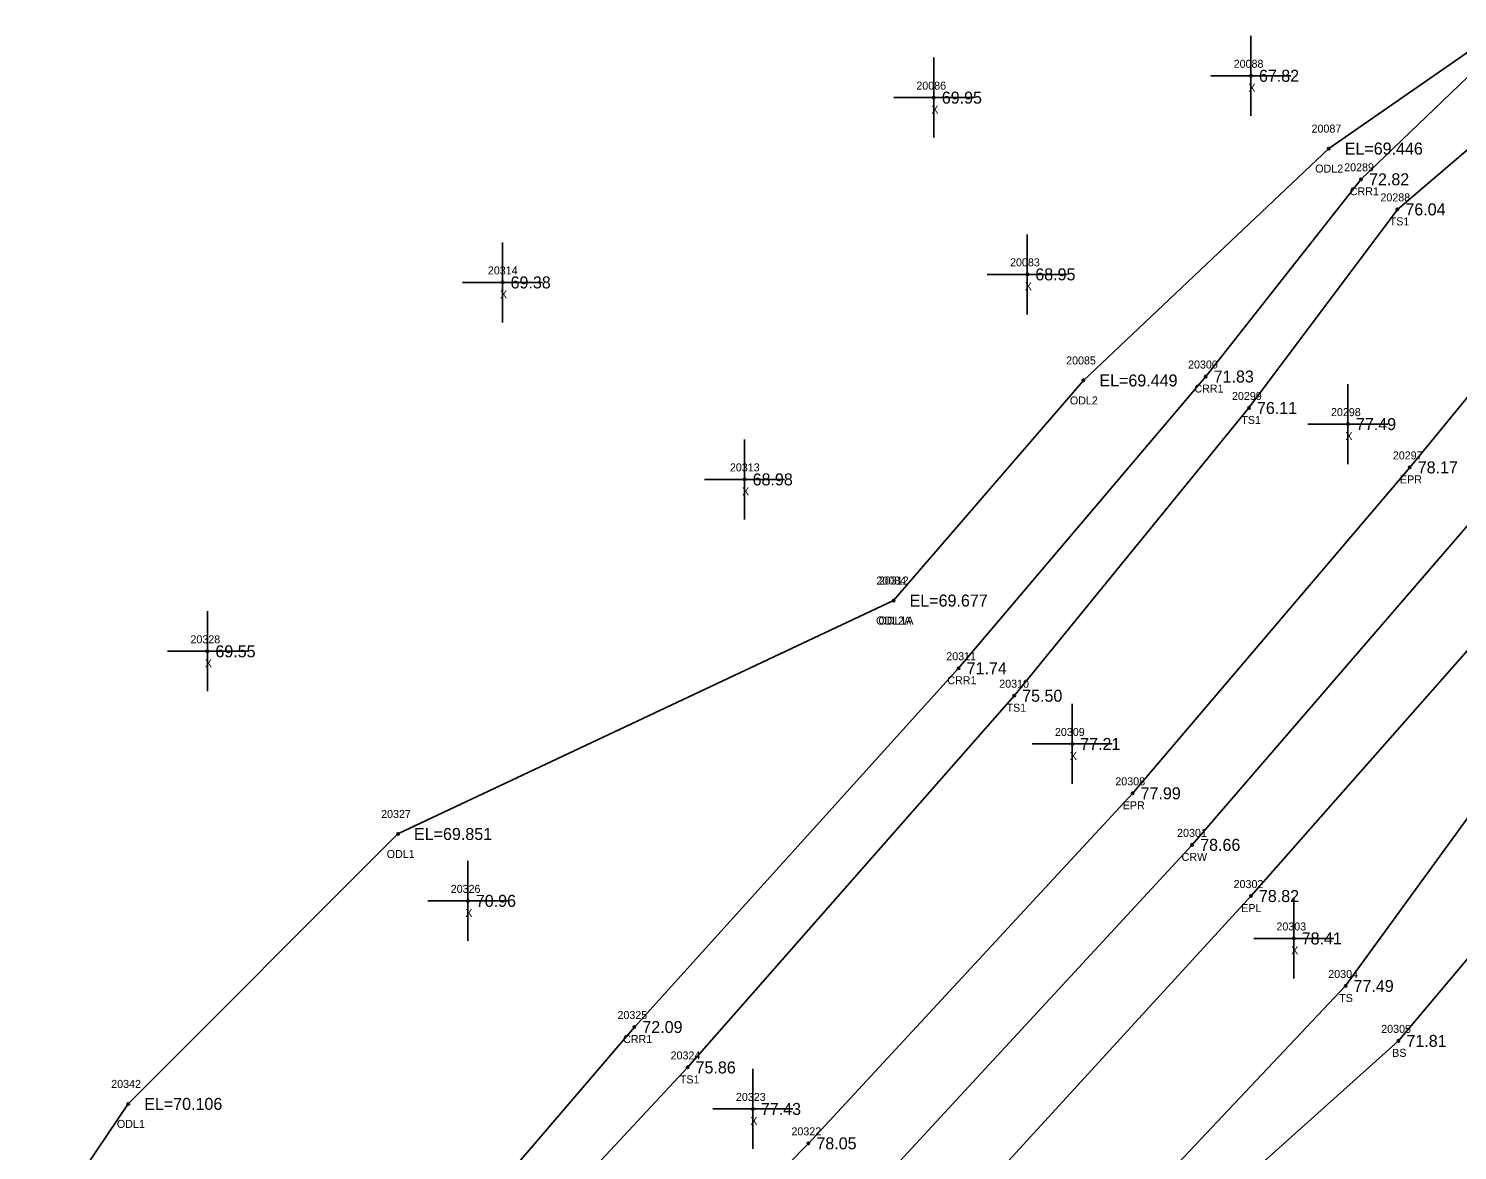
# Model space of a CAD drawing. Extents: x 2505300 to 2506184, y 912965 to 913825.
# Drawn here: x 2505552.8 to 2505731.4, y 913342.5 to 913482.7 of the extents above; entities that cross this region are included whole.
import ezdxf

# ---------------------------------------------------------------- set-up
doc = ezdxf.new("R2010")
doc.units = 0
for name, color, linetype in [('RD_DTM_BkLn1', 7, 'Continuous'), ('RD_DTM_BkLn2', 7, 'Continuous'), ('RD_DTM_BkLn_txCode', 7, 'Continuous'), ('RD_EX_H2O', 7, 'Continuous'), ('RD_EX_H2O_txCode', 7, 'Continuous'), ('RD_EX_Misc', 7, 'Continuous'), ('RD_EX_Misc_txCode', 7, 'Continuous'), ('RD_EX_Road', 7, 'Continuous'), ('RD_EX_Road_txCode', 7, 'Continuous'), ('RD_EX_TX_H2O_ELEV', 7, 'Continuous'), ('RD_EX_TX_Misc_ELEV', 7, 'Continuous'), ('RD_EX_TX_Road_ELEV', 7, 'Continuous'), ('RD_HC_Survey_ELEV', 7, 'Continuous'), ('RD_HC_Survey_txCode', 7, 'Continuous'), ('RD_SMD_Locator', 7, 'Continuous')]:
    doc.layers.add(name, color=color, linetype=linetype)

msp = doc.modelspace()

# ---------------------------------------------------------------- linework, layer by layer
at = {"layer": 'RD_DTM_BkLn1'}
msp.add_lwpolyline([(2505767.92, 913463.52), (2505733.49, 913421.6), (2505698.21, 913380.67), (2505657.08, 913336.16), (2505615.28, 913294.08), (2505578.04, 913257.66), (2505509.81, 913190.87), (2505437.56, 913120.73), (2505363.23, 913048.54)], dxfattribs=at)
at = {"layer": 'RD_DTM_BkLn2'}
for points in [[(2505753.71, 913473.94), (2505744.94, 913478.08), (2505723.86, 913460.1), (2505705.31, 913435.28), (2505675.97, 913399.31), (2505635.15, 913352.85), (2505596.03, 913310.85), (2505561.37, 913275.87), (2505492.57, 913207.56), (2505417.69, 913144.74), (2505344.31, 913068.67)], [(2505795.69, 913463.1), (2505792.51, 913445.22), (2505759.98, 913398.97), (2505723.99, 913356.17), (2505679.61, 913316.33), (2505634.47, 913275.19), (2505602.54, 913232.97), (2505592.24, 913228.82), (2505620.93, 913209.9)], [(2505778.84, 913452.68), (2505749.61, 913407.4), (2505717.38, 913363.03), (2505676.27, 913319.47), (2505630.56, 913278.36), (2505596.33, 913240.71), (2505582.14, 913231.32), (2505618.19, 913208.73)]]:
    msp.add_lwpolyline(points, dxfattribs=at)
at = {"layer": 'RD_EX_H2O'}
for points in [[(2505660.9, 913411.21), (2505684.62, 913438.72), (2505715.28, 913467.7), (2505742.46, 913486.6), (2505763.96, 913488.43), (2505794.61, 913469.83), (2505812.57, 913467.2), (2505833.64, 913450.28), (2505872.88, 913457.34), (2505893.17, 913479.86), (2505942.46, 913480.08), (2505995.98, 913475.04), (2506045.33, 913460.93), (2506077.87, 913439.29), (2506087.99, 913429.78), (2506108.19, 913381.27)], [(2505789.47, 913464.31), (2505758.18, 913486.1), (2505736.66, 913480.49), (2505719.32, 913463.86), (2505699.9, 913439.21), (2505669.03, 913402.75), (2505628.5, 913357.9), (2505593, 913316.39), (2505556.58, 913279.8), (2505487.72, 913211.38), (2505413.81, 913149.81), (2505341.31, 913072.1)], [(2505660.9, 913411.21), (2505598.96, 913382.03), (2505565.24, 913348.29), (2505539.28, 913309.84), (2505469.64, 913225.59)]]:
    msp.add_lwpolyline(points, dxfattribs=at)
at = {"layer": 'RD_EX_Misc'}
for p, q in [((2505705.56, 913471.8), (2505705.56, 913481.8)), ((2505665.92, 913469.07), (2505665.92, 913479.07)), ((2505700.56, 913476.8), (2505710.56, 913476.8)), ((2505660.92, 913474.07), (2505670.92, 913474.07)), ((2505677.61, 913446.98), (2505677.61, 913456.98)), ((2505612.03, 913445.97), (2505612.03, 913455.97)), ((2505607.03, 913450.97), (2505617.03, 913450.97)), ((2505672.61, 913451.98), (2505682.61, 913451.98)), ((2505717.68, 913428.26), (2505717.68, 913438.26)), ((2505712.68, 913433.26), (2505722.68, 913433.26)), ((2505642.28, 913421.35), (2505642.28, 913431.35)), ((2505637.28, 913426.35), (2505647.28, 913426.35)), ((2505575.14, 913399.86), (2505575.14, 913409.86)), ((2505570.14, 913404.86), (2505580.14, 913404.86)), ((2505683.22, 913388.28), (2505683.22, 913398.28)), ((2505678.22, 913393.28), (2505688.22, 913393.28)), ((2505607.69, 913368.67), (2505607.69, 913378.67)), ((2505602.69, 913373.67), (2505612.69, 913373.67)), ((2505710.9, 913363.97), (2505710.9, 913373.97)), ((2505705.9, 913368.97), (2505715.9, 913368.97)), ((2505643.31, 913342.66), (2505643.31, 913352.66)), ((2505638.31, 913347.66), (2505648.31, 913347.66))]:
    msp.add_line(p, q, dxfattribs=at)
at = {"layer": 'RD_EX_Road'}
for points in [[(2505758.23, 913470.96), (2505754.11, 913462.85), (2505725.4, 913427.85), (2505690.77, 913387.11), (2505650.25, 913343.36), (2505607.72, 913300.12), (2505570.97, 913264.99), (2505501.53, 913196.72), (2505431.76, 913128.83), (2505356.25, 913055.37)], [(2505777.56, 913455.88), (2505770.31, 913449.85), (2505741, 913414.45), (2505705.55, 913374.27), (2505664.83, 913329.82), (2505624.02, 913288.23), (2505585.62, 913250.63), (2505516.95, 913183.5), (2505444.27, 913113.56), (2505370.6, 913041.78)]]:
    msp.add_lwpolyline(points, dxfattribs=at)
at = {"layer": 'RD_SMD_Locator'}
for centre in [(2505705.56, 913476.8), (2505665.92, 913474.07), (2505715.28, 913467.7), (2505719.32, 913463.86), (2505723.86, 913460.1), (2505612.03, 913450.97), (2505677.61, 913451.98), (2505684.62, 913438.72), (2505699.9, 913439.21), (2505705.31, 913435.28), (2505717.68, 913433.26), (2505725.4, 913427.85), (2505642.28, 913426.35), (2505660.9, 913411.21), (2505660.9, 913411.21), (2505575.14, 913404.86), (2505669.03, 913402.75), (2505675.97, 913399.31), (2505683.22, 913393.28), (2505690.77, 913387.11), (2505598.96, 913382.03), (2505698.21, 913380.67), (2505705.55, 913374.27), (2505607.69, 913373.67), (2505710.9, 913368.97), (2505717.38, 913363.03), (2505628.5, 913357.9), (2505723.99, 913356.17), (2505635.15, 913352.85), (2505565.24, 913348.29), (2505643.31, 913347.66), (2505650.25, 913343.36)]:
    msp.add_circle(centre, 0.15, dxfattribs=at)

# ---------------------------------------------------------------- texts
at = {"layer": 'RD_DTM_BkLn_txCode'}
for s, p in [('20288', (2505721.74, 913461.1)), ('TS1', (2505722.9, 913458.1)), ('20299', (2505703.19, 913436.28)), ('TS1', (2505704.35, 913433.28)), ('20310', (2505674.1, 913400.31)), ('TS1', (2505675.01, 913397.31)), ('20304', (2505715.22, 913364.03)), ('TS', (2505716.59, 913361.03)), ('20305', (2505721.84, 913357.17)), ('20324', (2505633.03, 913353.85)), ('BS', (2505723.21, 913354.17)), ('TS1', (2505634.18, 913350.85))]:
    msp.add_text(s, height=1, dxfattribs=at).set_placement(p)
at = {"layer": 'RD_EX_H2O_txCode'}
for s, p in [('20087', (2505713.13, 913469.7)), ('ODL2', (2505713.59, 913464.7)), ('20289', (2505717.21, 913464.86)), ('CRR1', (2505717.91, 913461.86)), ('20085', (2505682.46, 913440.72)), ('20300', (2505697.7, 913440.21)), ('ODL2', (2505682.93, 913435.72)), ('CRR1', (2505698.48, 913437.21)), ('20084', (2505658.74, 913413.21)), ('20312', (2505659.06, 913413.21)), ('ODL2A', (2505658.71, 913408.21)), ('ODL1A', (2505659, 913408.21)), ('20311', (2505667.48, 913403.75)), ('CRR1', (2505667.61, 913400.75)), ('20327', (2505596.85, 913384.03)), ('ODL1', (2505597.55, 913379.03)), ('20325', (2505626.39, 913358.9)), ('CRR1', (2505627.09, 913355.9)), ('20342', (2505563.12, 913350.29)), ('ODL1', (2505563.83, 913345.29))]:
    msp.add_text(s, height=1, dxfattribs=at).set_placement(p)
at = {"layer": 'RD_EX_Misc_txCode'}
for s, p in [('20088', (2505703.4, 913477.8)), ('20086', (2505663.74, 913475.07)), ('X', (2505705.24, 913474.8)), ('X', (2505665.61, 913472.07)), ('20314', (2505610.19, 913451.97)), ('20083', (2505675.45, 913452.98)), ('X', (2505677.29, 913449.98)), ('X', (2505611.71, 913448.97)), ('20298', (2505715.56, 913434.26)), ('X', (2505717.36, 913431.26)), ('20313', (2505640.44, 913427.35)), ('X', (2505641.96, 913424.35)), ('20328', (2505573.02, 913405.86)), ('X', (2505574.82, 913402.86)), ('20309', (2505681.06, 913394.28)), ('X', (2505682.91, 913391.28)), ('20326', (2505605.55, 913374.67)), ('X', (2505607.37, 913371.67)), ('20303', (2505708.74, 913369.97)), ('X', (2505710.58, 913366.97)), ('20323', (2505641.19, 913348.66)), ('X', (2505642.99, 913345.66))]:
    msp.add_text(s, height=1, dxfattribs=at).set_placement(p)
at = {"layer": 'RD_EX_Road_txCode'}
for s, p in [('20297', (2505723.29, 913428.85)), ('EPR', (2505724.18, 913425.85)), ('20308', (2505688.61, 913388.11)), ('EPR', (2505689.54, 913385.11)), ('20302', (2505703.39, 913375.27)), ('EPL', (2505704.34, 913372.27)), ('20322', (2505648.13, 913344.36))]:
    msp.add_text(s, height=1, dxfattribs=at).set_placement(p)
at = {"layer": 'RD_EX_TX_H2O_ELEV'}
for s, p in [('EL=69.446', (2505717.28, 913466.95)), ('72.82', (2505720.32, 913463.11)), ('EL=69.449', (2505686.62, 913437.97)), ('71.83', (2505700.9, 913438.46)), ('EL=69.677', (2505662.9, 913410.46)), ('EL=69.677', (2505662.9, 913410.46)), ('71.74', (2505670.03, 913402)), ('EL=69.851', (2505600.96, 913381.28)), ('72.09', (2505629.5, 913357.15)), ('EL=70.106', (2505567.24, 913347.54))]:
    msp.add_text(s, height=1.5, dxfattribs=at).set_placement(p)
at = {"layer": 'RD_EX_TX_Misc_ELEV'}
for s, p in [('67.82', (2505706.56, 913476.05)), ('69.95', (2505666.92, 913473.32)), ('76.04', (2505724.86, 913459.35)), ('68.95', (2505678.61, 913451.23)), ('69.38', (2505613.03, 913450.22)), ('76.11', (2505706.31, 913434.53)), ('77.49', (2505718.68, 913432.51)), ('68.98', (2505643.28, 913425.6)), ('69.55', (2505576.14, 913404.11)), ('75.50', (2505676.97, 913398.56)), ('77.21', (2505684.22, 913392.53)), ('70.96', (2505608.69, 913372.92)), ('78.41', (2505711.9, 913368.22)), ('77.49', (2505718.38, 913362.28)), ('71.81', (2505724.99, 913355.42)), ('75.86', (2505636.15, 913352.1)), ('77.43', (2505644.31, 913346.91))]:
    msp.add_text(s, height=1.5, dxfattribs=at).set_placement(p)
at = {"layer": 'RD_EX_TX_Road_ELEV'}
for s, p in [('78.17', (2505726.4, 913427.1)), ('77.99', (2505691.77, 913386.36)), ('78.82', (2505706.55, 913373.52)), ('78.05', (2505651.25, 913342.61))]:
    msp.add_text(s, height=1.5, dxfattribs=at).set_placement(p)
at = {"layer": 'RD_HC_Survey_ELEV'}
msp.add_text('78.66', height=1.5, dxfattribs=at).set_placement((2505699.21, 913379.92))
at = {"layer": 'RD_HC_Survey_txCode'}
for s, p in [('20301', (2505696.33, 913381.67)), ('CRW', (2505696.89, 913378.67))]:
    msp.add_text(s, height=1, dxfattribs=at).set_placement(p)

doc.saveas('drawing.dxf')
